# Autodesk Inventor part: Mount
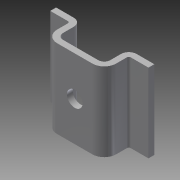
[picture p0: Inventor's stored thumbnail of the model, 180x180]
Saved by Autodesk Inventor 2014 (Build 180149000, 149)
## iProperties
Created: 2004-07
Part Number: Mount
Document SubType Name: Modeling
Designer: leeha
Manufacturer: Standard
Standards Organization: Custom
Material: Steel, Mild
Density: 7.86 g/cm^3
Mass: 511.026 g
Surface Area: 245.892 cm^2
Volume: 65.016 cm^3
Appearance: Steel
Author: Autodesk, Inc.
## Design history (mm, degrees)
sketch "Sketch1"
  geometry: L1 (-48.13, 10.945)-(-30.13, 10.945); L2 (-22.13, 2.945)-(-22.13, -8.033); L3 (-16.108, -14.055)-(19.848, -14.055); L4 (25.87, -8.033)-(25.87, 2.945); L5 (33.87, 10.945)-(51.87, 10.945); L6 (-48.13, 4.945)-(-30.13, 4.945); L7 (-28.13, 2.945)-(-28.13, -8.033); L8 (-16.108, -20.055)-(19.848, -20.055); L9 (31.87, -8.033)-(31.87, 2.945); L10 (33.87, 4.945)-(51.87, 4.945); L11 (-48.13, 10.945)-(-48.13, 4.945); L12 (51.87, 4.945)-(51.87, 10.945); A1 r 8 centre (-30.13, 2.945) between (-22.13, 2.945) and (-30.13, 10.945); A2 r 8 centre (33.87, 2.945) between (33.87, 10.945) and (25.87, 2.945); A3 r 6.022 centre (-16.108, -8.033) between (-22.13, -8.033) and (-16.108, -14.055); A4 r 6.022 centre (19.848, -8.033) between (19.848, -14.055) and (25.87, -8.033); A5 r 2 centre (-30.13, 2.945) between (-28.13, 2.945) and (-30.13, 4.945); A6 r 12.022 centre (-16.108, -8.033) between (-28.13, -8.033) and (-16.108, -20.055); A7 r 12.022 centre (19.848, -8.033) between (19.848, -20.055) and (31.87, -8.033); A8 r 2 centre (33.87, 2.945) between (33.87, 4.945) and (31.87, 2.945)
  constraints: 24 end point, 16 point on circle, 8 centre point, 8 tangent, 5 collinear, 5 parallel, 3 perpendicular, 2 equal radius, 1 horizontal, 8 other
  dimensions: "d1" = 8 radius of A1; "d3" = 6 distance between parallel lines of L1 L6; "d4" = 25 distance between parallel lines of L5 L3; "d5" = 60 distance between parallel lines of L9 L7; "d6" = 100 distance between parallel lines of L12 L11
extrude "Extrusion1" new body sketch "Sketch1" distance "d7" = 80; taper "d8" = 0 deg
sketch "Sketch2"
  geometry: L1 (35.956, 80)-(0, 80) reference; L2 (35.956, 0)-(35.956, 80) reference; C1 r 8 at (17.978, 40); 2 further points
  constraints: 2 midpoint, 1 centre point, 1 horizontal alignment, 1 vertical alignment
  dimensions: "d9" = 16 diameter of C1
extrude "Extrusion2" cut sketch "Sketch2" distance "d10" = 80; taper "d11" = 0 deg
sketch "Sketch3"
  geometry: C1 r 8 at (17.978, 40) reference; C2 r 14 at (17.978, 40)
  constraints: 1 centre point, 1 coincident
  dimensions: "d12" = 28 diameter of C2
split "Split1" sketch "Sketch3"
body "Solid1"
